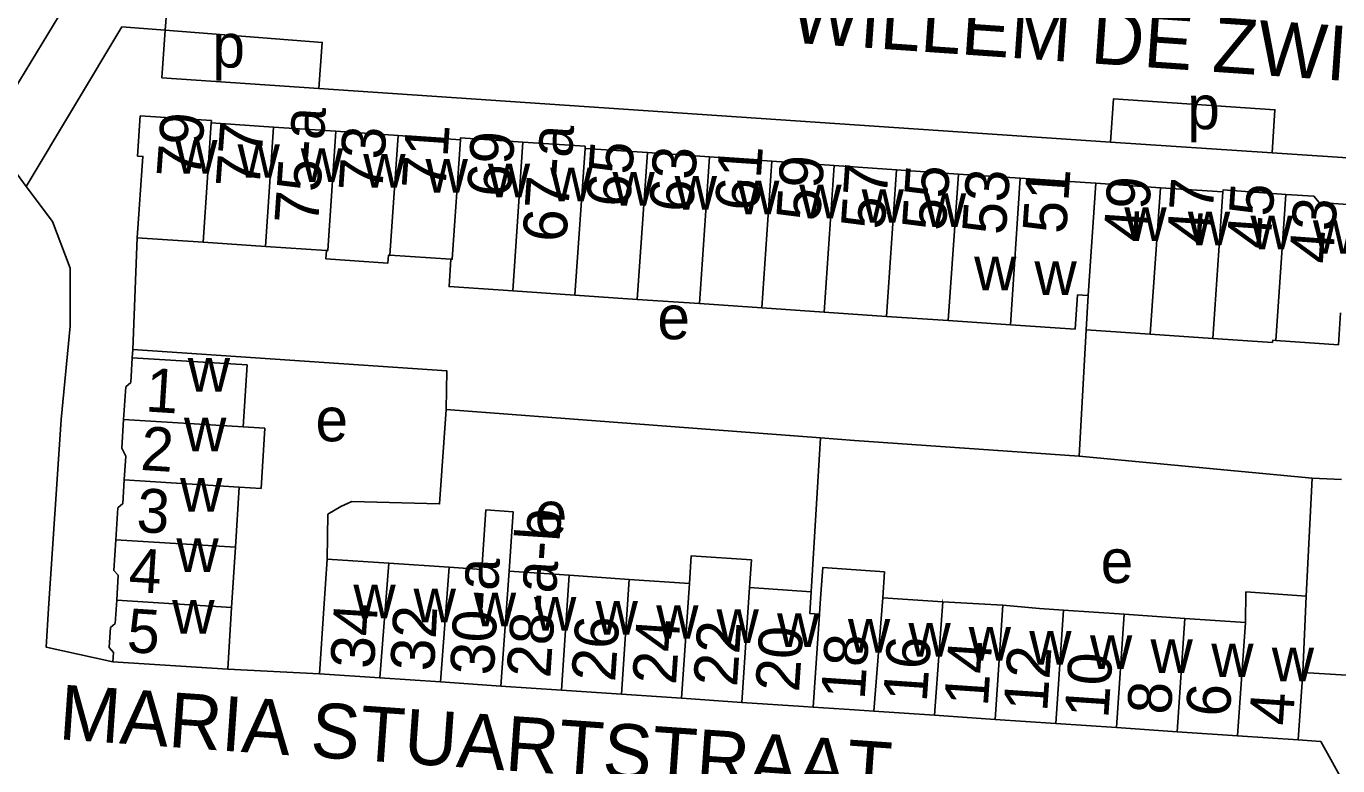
# Model space of a CAD drawing. Extents: x 159261 to 160849, y 382514 to 384534.
# Drawn here: x 160624.3 to 160744.1, y 382885.6 to 382953.2 of the extents above; entities that cross this region are included whole.
import ezdxf

# ---------------------------------------------------------------- set-up
doc = ezdxf.new("R2010")
doc.units = 0
for name, color, linetype in [('BLT_Basislijn', 7, 'Continuous'), ('BLT_Bebouwing', 7, 'Continuous'), ('BLT_Centroide', 7, 'Continuous'), ('BLT_Huisnummer', 7, 'Continuous'), ('BLT_Huisnummer_ tussenligend', 7, 'Continuous'), ('BLT_Huisnummer_reeks', 7, 'Continuous'), ('BLT_Onderverdeling_panden', 7, 'Continuous'), ('BLT_Straatnaam', 7, 'Continuous')]:
    doc.layers.add(name, color=color, linetype=linetype)

msp = doc.modelspace()

# ---------------------------------------------------------------- linework, layer by layer
at = {"layer": 'BLT_Basislijn'}
for p, q in [((160629.32, 382957.45), (160621.1, 382943.88)), ((160637.32, 382956.76), (160637.04, 382952.81)), ((160637.04, 382952.81), (160636.73, 382948.45)), ((160651.06, 382947.48), (160636.73, 382948.45)), ((160700, 382944.18), (160651.06, 382947.48)), ((160723.38, 382942.6), (160700, 382944.18)), ((160738.13, 382941.61), (160723.38, 382942.6)), ((160804.69, 382937.12), (160738.13, 382941.61)), ((160634.07, 382923.64), (160634.48, 382933.84)), ((160721.14, 382925.44), (160720.51, 382913.92)), ((160634.02, 382922.9), (160634.07, 382923.64)), ((160696.89, 382915.57), (160662.68, 382918.17)), ((160696.03, 382901.53), (160696.89, 382915.57)), ((160700, 382915.35), (160696.89, 382915.57)), ((160720.51, 382913.92), (160700, 382915.35)), ((160741.79, 382911.89), (160720.51, 382913.92)), ((160744.48, 382911.77), (160741.79, 382911.89)), ((160651.12, 382894.04), (160642.74, 382894.46))]:
    msp.add_line(p, q, dxfattribs=at)
for points in [[(160637.04, 382952.81), (160633.07, 382953.11), (160624.34, 382938.55)], [(160651.06, 382947.48), (160651.37, 382951.7), (160637.04, 382952.81)], [(160723.38, 382942.6), (160723.65, 382946.54), (160738.4, 382945.54), (160738.13, 382941.61)], [(160622.03, 382940.77), (160623.27, 382940), (160624.34, 382938.55)], [(160624.34, 382938.55), (160626.72, 382935.33), (160628.34, 382931.07), (160628.34, 382925.79), (160627.53, 382917.27), (160626.38, 382900), (160626.16, 382896.46), (160632.25, 382895.12)], [(160662.68, 382918.17), (160662.77, 382921.69), (160634.07, 382923.64)], [(160651.83, 382904.52), (160651.88, 382908.6), (160653.08, 382909.31), (160654.07, 382909.78), (160662.1, 382909.55), (160662.68, 382918.17)], [(160741.25, 382901.14), (160741.79, 382911.89)]]:
    msp.add_lwpolyline(points, dxfattribs=at)
at = {"layer": 'BLT_Bebouwing'}
for p, q in [((160646.92, 382943.97), (160641.23, 382944.36)), ((160652.62, 382943.59), (160646.92, 382943.97)), ((160658.31, 382943.2), (160652.62, 382943.59)), ((160664, 382942.8), (160658.31, 382943.2)), ((160681.07, 382941.63), (160675.38, 382942.02)), ((160686.76, 382941.24), (160681.07, 382941.63)), ((160692.45, 382940.85), (160686.76, 382941.24)), ((160698.14, 382940.46), (160692.45, 382940.85)), ((160703.83, 382940.06), (160698.14, 382940.46)), ((160709.49, 382939.67), (160703.83, 382940.06)), ((160709.49, 382939.67), (160715.12, 382939.29)), ((160715.12, 382939.29), (160721.07, 382938.89)), ((160721.07, 382938.89), (160722.03, 382938.83)), ((160727.93, 382938.43), (160733.65, 382938.04)), ((160651.76, 382932.69), (160646.18, 382933.07)), ((160663.13, 382931.9), (160657.56, 382932.28)), ((160674.46, 382928.62), (160668.78, 382929.01)), ((160680.15, 382928.23), (160674.46, 382928.62)), ((160685.84, 382927.84), (160680.15, 382928.23)), ((160721.35, 382928.57), (160720.36, 382928.64)), ((160721.14, 382925.44), (160721.35, 382928.57)), ((160691.53, 382927.46), (160685.84, 382927.84)), ((160697.22, 382927.07), (160691.53, 382927.46)), ((160702.91, 382926.68), (160697.22, 382927.07)), ((160708.55, 382926.3), (160714.25, 382925.91)), ((160732.73, 382924.67), (160727.01, 382925.05)), ((160643.45, 382905.59), (160643.8, 382911.09)), ((160643.1, 382900.1), (160643.45, 382905.59)), ((160651.83, 382904.52), (160657.47, 382904.14)), ((160657.47, 382904.14), (160662.96, 382903.77)), ((160668.45, 382903.4), (160673.93, 382903.03)), ((160673.93, 382903.03), (160679.42, 382902.66)), ((160702.57, 382900.97), (160702.73, 382903.35)), ((160679.42, 382902.66), (160684.91, 382902.29)), ((160690.4, 382901.91), (160696.03, 382901.53)), ((160708.07, 382900.6), (160702.57, 382900.97)), ((160708.02, 382900.77), (160708.01, 382900.77)), ((160713.53, 382900.29), (160708.07, 382900.6)), ((160740.95, 382894.17), (160741.25, 382901.14)), ((160713.55, 382900.29), (160713.53, 382900.29)), ((160716.88, 382900), (160713.55, 382900.29)), ((160719.08, 382899.85), (160716.88, 382900)), ((160724.62, 382899.48), (160719.08, 382899.85)), ((160730.16, 382899.1), (160724.62, 382899.48)), ((160735.7, 382898.73), (160730.16, 382899.1)), ((160642.74, 382894.46), (160632.25, 382895.12)), ((160656.65, 382893.66), (160651.12, 382894.04)), ((160662.18, 382893.29), (160656.65, 382893.66)), ((160667.7, 382892.92), (160662.18, 382893.29)), ((160673.23, 382892.54), (160667.7, 382892.92)), ((160678.71, 382892.17), (160673.23, 382892.54)), ((160684.2, 382891.8), (160678.71, 382892.17)), ((160689.69, 382891.43), (160684.2, 382891.8)), ((160695.32, 382891.05), (160689.69, 382891.43)), ((160695.32, 382891.05), (160696.22, 382891)), ((160700, 382890.74), (160696.22, 382891)), ((160701.76, 382890.62), (160700, 382890.74)), ((160707.3, 382890.25), (160701.76, 382890.62)), ((160712.84, 382889.87), (160707.3, 382890.25)), ((160718.38, 382889.5), (160712.84, 382889.87)), ((160723.92, 382889.12), (160718.38, 382889.5)), ((160729.46, 382888.75), (160723.92, 382889.12)), ((160734.99, 382888.37), (160729.46, 382888.75)), ((160740.53, 382888), (160734.99, 382888.37))]:
    msp.add_line(p, q, dxfattribs=at)
for points in [[(160641.23, 382944.36), (160641.25, 382944.55), (160634.75, 382944.98), (160634.5, 382941.31), (160635, 382941.28), (160634.48, 382933.84)], [(160669.69, 382942.6), (160664.01, 382942.99), (160664, 382942.8)], [(160675.38, 382942.02), (160675.39, 382942.21), (160669.69, 382942.6)], [(160722.03, 382938.83), (160727.93, 382938.43)], [(160739.38, 382937.81), (160733.66, 382938.22), (160733.65, 382938.04)], [(160739.38, 382937.81), (160741.95, 382937.64), (160742.44, 382937.07), (160745.07, 382936.89)], [(160634.48, 382933.84), (160640.49, 382933.44)], [(160640.49, 382933.44), (160646.18, 382933.07)], [(160657.56, 382932.28), (160657.43, 382932.28), (160657.38, 382931.55), (160651.71, 382931.94), (160651.76, 382932.69)], [(160668.78, 382929.01), (160662.96, 382929.4), (160663.13, 382931.9)], [(160714.25, 382925.91), (160720.14, 382925.51), (160720.36, 382928.64)], [(160744.39, 382927), (160744.19, 382924.08), (160738.47, 382924.47)], [(160708.55, 382926.3), (160702.91, 382926.68)], [(160727.01, 382925.05), (160721.14, 382925.44)], [(160738.17, 382924.3), (160732.73, 382924.67)], [(160738.17, 382924.3), (160738.19, 382924.49), (160738.47, 382924.47)], [(160633.23, 382917.27), (160633.42, 382920.24), (160633.88, 382920.65), (160634.02, 382922.9)], [(160644.15, 382916.58), (160644.51, 382922.24), (160634.02, 382922.9)], [(160633.29, 382911.75), (160633.43, 382913.9), (160633.07, 382914.63), (160633.23, 382917.27)], [(160643.8, 382911.09), (160645.79, 382910.96), (160646.13, 382916.46), (160644.15, 382916.58)], [(160632.53, 382906.28), (160632.71, 382909.19), (160633.15, 382909.58), (160633.29, 382911.75)], [(160662.96, 382903.77), (160665.96, 382903.57), (160666.33, 382909.01), (160668.81, 382908.84), (160668.45, 382903.4)], [(160632.6, 382900.76), (160632.74, 382903.04), (160632.35, 382903.48), (160632.53, 382906.28)], [(160651.12, 382894.04), (160651.53, 382900), (160651.83, 382904.52)], [(160684.91, 382902.29), (160685.08, 382904.81), (160690.57, 382904.44), (160690.4, 382901.91)], [(160696.83, 382900), (160696.92, 382901.35), (160697.09, 382903.73), (160702.73, 382903.35)], [(160632.25, 382895.12), (160632.31, 382895.99), (160631.91, 382896.44), (160632.02, 382898.26), (160632.46, 382898.64), (160632.6, 382900.76)], [(160696.03, 382901.53), (160695.9, 382899.55), (160696.8, 382899.49)], [(160741.25, 382901.14), (160735.75, 382901.51), (160735.7, 382898.73)], [(160643.1, 382900.1), (160642.74, 382894.46)], [(160696.8, 382899.49), (160696.83, 382900)], [(160740.95, 382894.17), (160744.93, 382893.9), (160745.91, 382893.19), (160746.59, 382891.89), (160749.28, 382893.37), (160752.36, 382887.79), (160749.48, 382886.2)], [(160744.89, 382883.67), (160742.58, 382887.86), (160740.53, 382888)]]:
    msp.add_lwpolyline(points, dxfattribs=at)
at = {"layer": 'BLT_Onderverdeling_panden'}
for p, q in [((160640.49, 382933.44), (160641.23, 382944.36)), ((160646.18, 382933.07), (160646.92, 382943.97)), ((160657.56, 382932.28), (160658.31, 382943.2)), ((160668.78, 382929.01), (160669.69, 382942.6)), ((160674.46, 382928.62), (160675.38, 382942.02)), ((160680.15, 382928.23), (160681.07, 382941.63)), ((160685.84, 382927.84), (160686.76, 382941.24)), ((160691.53, 382927.46), (160692.45, 382940.85)), ((160697.22, 382927.07), (160698.14, 382940.46)), ((160702.91, 382926.68), (160703.83, 382940.06)), ((160714.25, 382925.91), (160715.12, 382939.29)), ((160721.35, 382928.57), (160722.03, 382938.83)), ((160727.01, 382925.05), (160727.93, 382938.43)), ((160732.73, 382924.67), (160733.65, 382938.04)), ((160738.47, 382924.47), (160739.38, 382937.81)), ((160644.15, 382916.58), (160633.23, 382917.27)), ((160643.8, 382911.09), (160633.29, 382911.75)), ((160643.45, 382905.59), (160632.53, 382906.28)), ((160656.65, 382893.66), (160657.47, 382904.14)), ((160662.18, 382893.29), (160662.96, 382903.77)), ((160667.7, 382892.92), (160668.45, 382903.4)), ((160673.23, 382892.54), (160673.93, 382903.03)), ((160678.71, 382892.17), (160679.42, 382902.66)), ((160684.2, 382891.8), (160684.91, 382902.29)), ((160689.69, 382891.43), (160690.4, 382901.91)), ((160643.1, 382900.1), (160632.6, 382900.76)), ((160702.57, 382900.97), (160701.76, 382890.62)), ((160708.07, 382900.6), (160707.3, 382890.25)), ((160696.8, 382899.49), (160696.22, 382891)), ((160713.55, 382900.29), (160712.84, 382889.87)), ((160719.08, 382899.85), (160718.38, 382889.5)), ((160724.62, 382899.48), (160723.92, 382889.12)), ((160730.16, 382899.1), (160729.46, 382888.75)), ((160735.7, 382898.73), (160734.99, 382888.37)), ((160740.95, 382894.17), (160740.53, 382888))]:
    msp.add_line(p, q, dxfattribs=at)
for points in [[(160651.76, 382932.69), (160651.87, 382932.69), (160652.62, 382943.59)], [(160663.13, 382931.9), (160663.25, 382931.89), (160664, 382942.8)], [(160709.49, 382939.67), (160708.55, 382926.3)]]:
    msp.add_lwpolyline(points, dxfattribs=at)

# ---------------------------------------------------------------- texts
at = {"layer": 'BLT_Centroide'}
for s, p in [('p', (160641.34, 382949.4)), ('p', (160730.39, 382943.77)), ('w', (160637.94, 382939.72)), ('w', (160643.64, 382939.33)), ('w', (160649.41, 382938.94)), ('w', (160655.12, 382938.44)), ('w', (160660.81, 382937.97)), ('w', (160666.5, 382937.56)), ('w', (160672.19, 382937.19)), ('w', (160677.88, 382936.8)), ('w', (160683.56, 382936.41)), ('w', (160689.27, 382936)), ('w', (160694.95, 382935.62)), ('w', (160700.64, 382935.22)), ('w', (160706.33, 382934.84)), ('w', (160724.64, 382933.56)), ('w', (160730.44, 382933.16)), ('w', (160736.16, 382932.8)), ('w', (160741.86, 382932.39)), ('w', (160710.92, 382929.07)), ('w', (160716.43, 382928.63)), ('e', (160681.99, 382924.59)), ('w', (160639.09, 382919.81)), ('e', (160650.76, 382915.27)), ('w', (160638.75, 382914.34)), ('w', (160638.39, 382908.84)), ('e', (160670.78, 382906.68)), ('w', (160638.05, 382903.34)), ('e', (160722.48, 382902.33)), ('w', (160654.22, 382899.11)), ('w', (160659.72, 382898.73)), ('w', (160637.67, 382897.69)), ('w', (160665.22, 382898.36)), ('w', (160670.72, 382897.98)), ('w', (160676.34, 382897.61)), ('w', (160681.88, 382897.23)), ('w', (160687.39, 382896.86)), ('w', (160692.92, 382896.48)), ('w', (160699.39, 382895.98)), ('w', (160704.92, 382895.61)), ('w', (160710.42, 382895.25)), ('w', (160715.95, 382894.88)), ('w', (160721.5, 382894.48)), ('w', (160727.03, 382894.11)), ('w', (160732.58, 382893.73)), ('w', (160738.11, 382893.36))]:
    msp.add_text(s, height=4, dxfattribs=at).set_placement(p)
at = {"layer": 'BLT_Huisnummer'}
for s, rotation, p in [('79', 85.8278, (160640.22, 382939.21)), ('71', 86.0864, (160662.62, 382938.18)), ('63', 86.0864, (160685.23, 382936.12)), ('59', 86.0864, (160696.83, 382935.31)), ('55', 86.0842, (160708.31, 382934.42)), ('51', 86.0842, (160719.32, 382934.15)), ('47', 86.0872, (160732.51, 382933.2)), ('43', 85.8285, (160743.67, 382931.42)), ('1', 356.3665, (160635.16, 382918)), ('2', 356.3665, (160634.71, 382912.66)), ('3', 356.3665, (160634.34, 382907.01)), ('4', 356.358, (160633.62, 382901.55)), ('5', 356.3614, (160633.46, 382896.03)), ('34', 86.4417, (160656.09, 382894.43)), ('26', 86.1286, (160678.12, 382893.24)), ('22', 86.127, (160689.26, 382892.8)), ('18', 86.1286, (160700.91, 382891.61)), ('14', 86.1272, (160712.17, 382890.99)), ('10', 86.1272, (160723.17, 382889.9)), ('4', 86.1237, (160740.02, 382889.24))]:
    msp.add_text(s, height=4, rotation=rotation, dxfattribs=at).set_placement(p)
at = {"layer": 'BLT_Huisnummer_ tussenligend'}
for s, rotation, p in [('77', 85.832, (160645.63, 382938.31)), ('73', 86.0864, (160656.85, 382937.97)), ('69', 86.0864, (160668.57, 382937.5)), ('65', 86.0864, (160679.48, 382936.59)), ('61', 86.0864, (160691.23, 382936.23)), ('57', 86.0688, (160702.73, 382934.55)), ('53', 86.0842, (160713.8, 382934.05)), ('49', 86.0849, (160726.71, 382933.38)), ('45', 86.0863, (160737.97, 382932.76)), ('32', 86.9859, (160661.58, 382894.22)), ('24', 86.127, (160683.68, 382892.98)), ('20', 86.1286, (160694.92, 382892.31)), ('16', 86.1272, (160706.59, 382891.39)), ('12', 86.1272, (160717.59, 382890.51)), ('8', 86.1237, (160728.88, 382890.24)), ('6', 86.1237, (160734.25, 382890.03))]:
    msp.add_text(s, height=4, rotation=rotation, dxfattribs=at).set_placement(p)
at = {"layer": 'BLT_Huisnummer_reeks'}
for s, rotation, p in [('75-a', 86.0868, (160650.99, 382935)), ('67-a', 86.0879, (160673.65, 382933.38)), ('28-a-b', 86.1286, (160672.2, 382893.59)), ('30-a', 86.9859, (160667.04, 382893.84))]:
    msp.add_text(s, height=4, rotation=rotation, dxfattribs=at).set_placement(p)
at = {"layer": 'BLT_Straatnaam'}
for s, rotation, p in [('WILLEM DE ZWIJGERSTRAAT', 356.041, (160694.06, 382951.69)), ('MARIA STUARTSTRAAT', 356.0037, (160627.23, 382888.07))]:
    msp.add_text(s, height=5, rotation=rotation, dxfattribs=at).set_placement(p)

doc.saveas('drawing.dxf')
